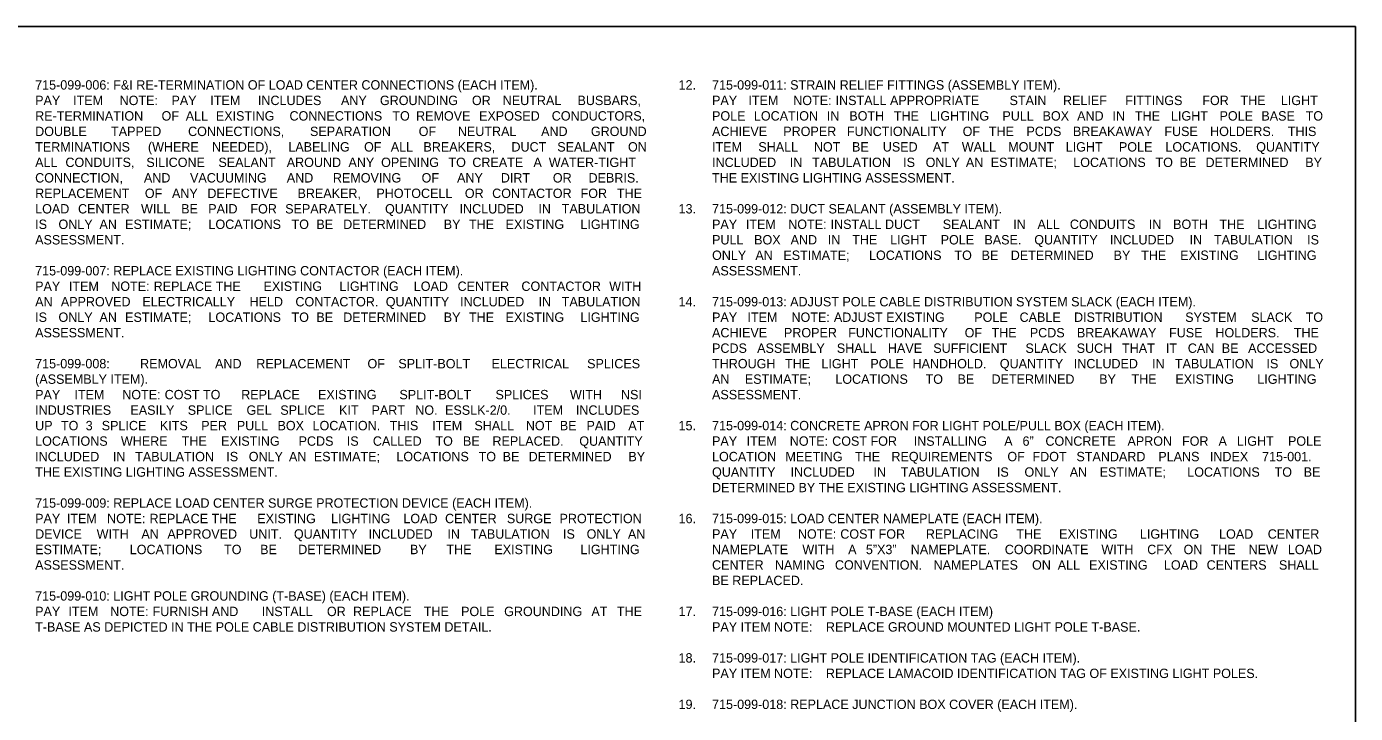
# Model space of a CAD drawing. Extents: x -55 to 2471539, y -90 to 3608906.
# Drawn here: x 549 to 1540, y 448 to 960 of the extents above; entities that cross this region are included whole.
import ezdxf

# ---------------------------------------------------------------- set-up
doc = ezdxf.new("R2010")
doc.units = 0
doc.layers.add('NonPlottingEle_dp', color=7, linetype='Continuous')
doc.layers.add('TextNotes', color=7, linetype='Continuous')

msp = doc.modelspace()

# ---------------------------------------------------------------- linework, layer by layer
at = {"layer": 'NonPlottingEle_dp'}
msp.add_lwpolyline([(0, 0), (0, 960), (1540, 960), (1540, 0)], dxfattribs=at)

# ---------------------------------------------------------------- texts
at = {"layer": 'TextNotes'}
for s, p in [('715-099-006: F&I RE-TERMINATION OF LOAD CENTER CONNECTIONS (EACH ITEM).', (555, 913)), ('12.', (1035.02, 913)), ('715-099-011: STRAIN RELIEF FITTINGS (ASSEMBLY ITEM).', (1060, 913)), ('PAY ', (555, 901.45)), ('ITEM ', (583.33, 901.45)), ('NOTE: ', (618.03, 901.45)), ('PAY ', (656.71, 901.45)), ('ITEM ', (685.68, 901.45)), ('INCLUDES ', (721.21, 901.45)), ('ANY ', (783.17, 901.45)), ('GROUNDING ', (812.22, 901.45)), ('OR ', (880.85, 901.45)), ('NEUTRAL ', (903.86, 901.45)), ('BUSBARS, ', (959.62, 901.45)), ('PAY ', (1060, 901.45)), ('ITEM ', (1087.09, 901.45)), ('NOTE:', (1120.56, 901.45)), (' INSTALL APPROPRIATE ', (1149.59, 901.45)), ('STAIN ', (1281.96, 901.45)), ('RELIEF ', (1321.82, 901.45)), ('FITTINGS ', (1368.29, 901.45)), ('FOR ', (1425.77, 901.45)), ('THE ', (1454.27, 901.45)), ('LIGHT ', (1484.37, 901.45)), ('RE-TERMINATION ', (555, 889.9)), ('OF ', (649.32, 889.9)), ('ALL ', (667.35, 889.9)), ('EXISTING ', (689.8, 889.9)), ('CONNECTIONS ', (744.75, 889.9)), ('TO ', (821.49, 889.9)), ('REMOVE ', (839.17, 889.9)), ('EXPOSED ', (886.18, 889.9)), ('CONDUCTORS, ', (940.41, 889.9)), ('POLE ', (1060, 889.9)), ('LOCATION ', (1091.23, 889.9)), ('IN ', (1145.64, 889.9)), ('BOTH ', (1162.41, 889.9)), ('THE ', (1195.61, 889.9)), ('LIGHTING ', (1222.5, 889.9)), ('PULL ', (1276.62, 889.9)), ('BOX ', (1306.59, 889.9)), ('AND ', (1332.37, 889.9)), ('IN ', (1358.72, 889.9)), ('THE ', (1375.49, 889.9)), ('LIGHT ', (1402.38, 889.9)), ('POLE ', (1438.62, 889.9)), ('BASE ', (1469.84, 889.9)), ('TO ', (1502.86, 889.9)), ('DOUBLE ', (555, 878.35)), ('TAPPED ', (611.64, 878.35)), ('CONNECTIONS, ', (669.09, 878.35)), ('SEPARATION ', (760.05, 878.35)), ('OF ', (841.16, 878.35)), ('NEUTRAL ', (870.36, 878.35)), ('AND ', (932.47, 878.35)), ('GROUND ', (969.61, 878.35)), ('ACHIEVE ', (1060, 878.35)), ('PROPER ', (1113.14, 878.35)), ('FUNCTIONALITY ', (1160.59, 878.35)), ('OF ', (1246.99, 878.35)), ('THE ', (1266.54, 878.35)), ('PCDS ', (1294.58, 878.35)), ('BREAKAWAY ', (1329.23, 878.35)), ('FUSE ', (1397.46, 878.35)), ('HOLDERS. ', (1431.57, 878.35)), ('THIS ', (1489.55, 878.35)), ('TERMINATIONS ', (555, 866.8)), ('(WHERE ', (639.14, 866.8)), ('NEEDED), ', (686.93, 866.8)), ('LABELING ', (743.91, 866.8)), ('OF ', (800.37, 866.8)), ('ALL ', (820.32, 866.8)), ('BREAKERS, ', (844.69, 866.8)), ('DUCT ', (910.35, 866.8)), ('SEALANT ', (944.54, 866.8)), ('ON ', (997.3, 866.8)), ('ITEM ', (1060, 866.8)), ('SHALL ', (1094.54, 866.8)), ('NOT ', (1135.96, 866.8)), ('BE ', (1164.42, 866.8)), ('USED ', (1187.4, 866.8)), ('AT ', (1224.78, 866.8)), ('WALL ', (1246.34, 866.8)), ('MOUNT ', (1280.97, 866.8)), ('LIGHT ', (1323.86, 866.8)), ('POLE ', (1363.56, 866.8)), ('LOCATIONS. ', (1398.25, 866.8)), ('QUANTITY ', (1465.96, 866.8)), ('ALL ', (555, 855.25)), ('CONDUITS, ', (577.58, 855.25)), ('SILICONE ', (637.96, 855.25)), ('SEALANT ', (691.72, 855.25)), ('AROUND ', (742.69, 855.25)), ('ANY ', (788.75, 855.25)), ('OPENING ', (813.1, 855.25)), ('TO ', (863.36, 855.25)), ('CREATE ', (881.17, 855.25)), ('A ', (926.74, 855.25)), ('WATER-TIGHT ', (938.22, 855.25)), ('INCLUDED ', (1060, 855.25)), ('IN ', (1117.98, 855.25)), ('TABULATION ', (1134.64, 855.25)), ('IS ', (1202.58, 855.25)), ('ONLY ', (1219.37, 855.25)), ('AN ', (1249.35, 855.25)), ('ESTIMATE; ', (1267.89, 855.25)), ('LOCATIONS ', (1329.47, 855.25)), ('TO ', (1390.85, 855.25)), ('BE ', (1408.78, 855.25)), ('DETERMINED ', (1428.18, 855.25)), ('BY ', (1502.59, 855.25)), ('CONNECTION, ', (555, 843.7)), ('AND ', (636.14, 843.7)), ('VACUUMING ', (670.54, 843.7)), ('AND ', (742.73, 843.7)), ('REMOVING ', (777.13, 843.7)), ('OF ', (843.31, 843.7)), ('ANY ', (869.77, 843.7)), ('DIRT ', (902.41, 843.7)), ('OR ', (941.24, 843.7)), ('DEBRIS. ', (967.85, 843.7)), ('THE EXISTING LIGHTING ASSESSMENT.', (1060, 843.7)), ('REPLACEMENT ', (555, 832.15)), ('OF ', (636.84, 832.15)), ('ANY ', (657.07, 832.15)), ('DEFECTIVE ', (683.49, 832.15)), ('BREAKER, ', (750.73, 832.15)), ('PHOTOCELL ', (809.59, 832.15)), ('OR ', (875.57, 832.15)), ('CONTACTOR ', (895.95, 832.15)), ('FOR ', (961.93, 832.15)), ('THE ', (989.03, 832.15)), ('LOAD ', (555, 820.6)), ('CENTER ', (586.99, 820.6)), ('WILL ', (633.99, 820.6)), ('BE ', (663.94, 820.6)), ('PAID ', (684.13, 820.6)), ('FOR ', (715.59, 820.6)), ('SEPARATELY. ', (741.53, 820.6)), ('QUANTITY ', (816.04, 820.6)), ('INCLUDED ', (871.65, 820.6)), ('IN ', (930.41, 820.6)), ('TABULATION ', (947.86, 820.6)), ('13.', (1035.02, 820.6)), ('715-099-012: DUCT SEALANT (ASSEMBLY ITEM).', (1060, 820.6)), ('IS ', (555, 809.05)), ('ONLY ', (572.4, 809.05)), ('AN ', (602.97, 809.05)), ('ESTIMATE; ', (622.11, 809.05)), ('LOCATIONS ', (684.3, 809.05)), ('TO ', (746.27, 809.05)), ('BE ', (764.81, 809.05)), ('DETERMINED ', (784.81, 809.05)), ('BY ', (859.82, 809.05)), ('THE ', (878.62, 809.05)), ('EXISTING ', (905.99, 809.05)), ('LIGHTING ', (961.79, 809.05)), ('PAY ', (1060, 809.05)), ('ITEM ', (1085.22, 809.05)), ('NOTE:', (1116.82, 809.05)), (' INSTALL DUCT ', (1145.86, 809.05)), ('SEALANT ', (1232.1, 809.05)), ('IN ', (1284.66, 809.05)), ('ALL ', (1302.79, 809.05)), ('CONDUITS ', (1326.96, 809.05)), ('IN ', (1385.87, 809.05)), ('BOTH ', (1404, 809.05)), ('THE ', (1438.55, 809.05)), ('LIGHTING ', (1466.79, 809.05)), ('ASSESSMENT.', (555, 797.5)), ('PULL ', (1060, 797.5)), ('BOX ', (1091.4, 797.5)), ('AND ', (1118.61, 797.5)), ('IN ', (1146.38, 797.5)), ('THE ', (1164.58, 797.5)), ('LIGHT ', (1192.89, 797.5)), ('POLE ', (1230.56, 797.5)), ('BASE. ', (1263.21, 797.5)), ('QUANTITY ', (1300.41, 797.5)), ('INCLUDED ', (1356.78, 797.5)), ('IN ', (1416.31, 797.5)), ('TABULATION ', (1434.51, 797.5)), ('IS ', (1503.99, 797.5)), ('ONLY ', (1060, 785.95)), ('AN ', (1092.31, 785.95)), ('ESTIMATE; ', (1113.2, 785.95)), ('LOCATIONS ', (1177.12, 785.95)), ('TO ', (1240.84, 785.95)), ('BE ', (1261.11, 785.95)), ('DETERMINED ', (1282.85, 785.95)), ('BY ', (1359.6, 785.95)), ('THE ', (1380.14, 785.95)), ('EXISTING ', (1409.25, 785.95)), ('LIGHTING ', (1466.79, 785.95)), ('715-099-007: REPLACE EXISTING LIGHTING CONTACTOR (EACH ITEM).', (555, 774.4)), ('ASSESSMENT.', (1060, 774.4)), ('PAY ', (555, 762.85)), ('ITEM ', (580.2, 762.85)), ('NOTE:', (611.78, 762.85)), (' REPLACE THE ', (640.81, 762.85)), ('EXISTING ', (725.38, 762.85)), ('LIGHTING ', (782.03, 762.85)), ('LOAD ', (837.48, 762.85)), ('CENTER ', (870.14, 762.85)), ('CONTACTOR ', (917.79, 762.85)), ('WITH ', (983.27, 762.85)), ('AN ', (555, 751.3)), ('APPROVED ', (574.15, 751.3)), ('ELECTRICALLY ', (634.99, 751.3)), ('HELD ', (714.94, 751.3)), ('CONTACTOR. ', (749.18, 751.3)), ('QUANTITY ', (816.57, 751.3)), ('INCLUDED ', (872.01, 751.3)), ('IN ', (930.59, 751.3)), ('TABULATION ', (947.86, 751.3)), ('14.', (1035.02, 751.3)), ('715-099-013: ADJUST POLE CABLE DISTRIBUTION SYSTEM SLACK (EACH ITEM).', (1060, 751.3)), ('IS ', (555, 739.75)), ('ONLY ', (572.4, 739.75)), ('AN ', (602.97, 739.75)), ('ESTIMATE; ', (622.11, 739.75)), ('LOCATIONS ', (684.3, 739.75)), ('TO ', (746.27, 739.75)), ('BE ', (764.81, 739.75)), ('DETERMINED ', (784.81, 739.75)), ('BY ', (859.82, 739.75)), ('THE ', (878.62, 739.75)), ('EXISTING ', (905.99, 739.75)), ('LIGHTING ', (961.79, 739.75)), ('PAY ', (1060, 739.75)), ('ITEM ', (1086.44, 739.75)), ('NOTE:', (1119.27, 739.75)), (' ADJUST EXISTING ', (1148.3, 739.75)), ('POLE ', (1255.64, 739.75)), ('CABLE ', (1289.44, 739.75)), ('DISTRIBUTION ', (1330.06, 739.75)), ('SYSTEM ', (1413.01, 739.75)), ('SLACK ', (1462.22, 739.75)), ('TO ', (1502.86, 739.75)), ('ASSESSMENT.', (555, 728.2)), ('ACHIEVE ', (1060, 728.2)), ('PROPER ', (1113.64, 728.2)), ('FUNCTIONALITY ', (1161.58, 728.2)), ('OF ', (1248.48, 728.2)), ('THE ', (1268.53, 728.2)), ('PCDS ', (1297.07, 728.2)), ('BREAKAWAY ', (1332.22, 728.2)), ('FUSE ', (1400.95, 728.2)), ('HOLDERS. ', (1435.55, 728.2)), ('THE ', (1494.03, 728.2)), ('PCDS ', (1060, 716.65)), ('ASSEMBLY ', (1093.64, 716.65)), ('SHALL ', (1153.08, 716.65)), ('SUFFICIENT ', (1225.08, 716.65)), ('SLACK ', (1293.82, 716.65)), ('SUCH ', (1332.03, 716.65)), ('CAN ', (1414.93, 716.65)), ('ACCESSED ', (1459.95, 716.65)), ('HAVE ', (1191.19, 716.65)), ('THAT ', (1365.89, 716.65)), ('IT ', (1398.57, 716.65)), ('BE ', (1440.29, 716.65)), ('715-099-008: ', (555, 705.1)), ('REMOVAL ', (633.3, 705.1)), ('AND ', (689.22, 705.1)), ('REPLACEMENT ', (719.97, 705.1)), ('OF ', (802.94, 705.1)), ('SPLIT-BOLT ', (825.96, 705.1)), ('ELECTRICAL ', (895.53, 705.1)), ('SPLICES ', (966.8, 705.1)), ('THROUGH ', (1060, 705.1)), ('THE ', (1114.45, 705.1)), ('LIGHT ', (1141.6, 705.1)), ('POLE ', (1178.1, 705.1)), ('HANDHOLD. ', (1209.59, 705.1)), ('QUANTITY ', (1274.7, 705.1)), ('INCLUDED ', (1329.91, 705.1)), ('IN ', (1388.27, 705.1)), ('TABULATION ', (1405.31, 705.1)), ('IS ', (1473.64, 705.1)), ('ONLY ', (1490.82, 705.1)), ('(ASSEMBLY ITEM).', (555, 693.55)), ('AN ', (1060, 693.55)), ('ESTIMATE; ', (1084.47, 693.55)), ('LOCATIONS ', (1151.99, 693.55)), ('TO ', (1219.29, 693.55)), ('BE ', (1243.16, 693.55)), ('DETERMINED ', (1268.49, 693.55)), ('BY ', (1348.83, 693.55)), ('THE ', (1372.96, 693.55)), ('EXISTING ', (1405.66, 693.55)), ('LIGHTING ', (1466.79, 693.55)), ('PAY ', (555, 682)), ('ITEM ', (584.31, 682)), ('NOTE:', (619.99, 682)), (' COST TO ', (649.03, 682)), ('REPLACE ', (708.72, 682)), ('EXISTING ', (766, 682)), ('SPLIT-BOLT ', (826.76, 682)), ('SPLICES ', (898.44, 682)), ('WITH ', (953.99, 682)), ('NSI ', (992.06, 682)), ('ASSESSMENT.', (1060, 682)), ('INDUSTRIES ', (555, 670.45)), ('EASILY ', (626.07, 670.45)), ('SPLICE ', (668.84, 670.45)), ('GEL ', (712.69, 670.45)), ('SPLICE ', (737.91, 670.45)), ('KIT ', (781.76, 670.45)), ('PART ', (805.95, 670.45)), ('NO. ', (838.61, 670.45)), ('ESSLK-2/0. ', (860.81, 670.45)), ('ITEM ', (926.52, 670.45)), ('INCLUDES ', (958.42, 670.45)), ('UP ', (555, 658.9)), ('TO ', (574.26, 658.9)), ('3 ', (592.69, 658.9)), ('SPLICE ', (604.66, 658.9)), ('KITS ', (648.07, 658.9)), ('PER ', (678.89, 658.9)), ('PULL ', (705.45, 658.9)), ('BOX ', (735.81, 658.9)), ('LOCATION. ', (761.97, 658.9)), ('THIS ', (819.52, 658.9)), ('ITEM ', (851.26, 658.9)), ('SHALL ', (882.71, 658.9)), ('NOT ', (921.06, 658.9)), ('BE ', (946.43, 658.9)), ('PAID ', (966.33, 658.9)), ('AT ', (997.51, 658.9)), ('15.', (1035.02, 658.9)), ('715-099-014: CONCRETE APRON FOR LIGHT POLE/PULL BOX (EACH ITEM).', (1060, 658.9)), ('LOCATIONS ', (555, 647.35)), ('WHERE ', (618.98, 647.35)), ('THE ', (664.35, 647.35)), ('EXISTING ', (693.73, 647.35)), ('PCDS ', (751.54, 647.35)), ('IS ', (787.53, 647.35)), ('CALLED ', (806.94, 647.35)), ('TO ', (853.63, 647.35)), ('BE ', (874.17, 647.35)), ('REPLACED. ', (896.18, 647.35)), ('QUANTITY ', (960.96, 647.35)), ('PAY ', (1060, 647.35)), ('ITEM ', (1085.81, 647.35)), ('NOTE:', (1118, 647.35)), (' COST FOR ', (1147.03, 647.35)), ('INSTALLING ', (1210.44, 647.35)), ('A ', (1278, 647.35)), ('6” ', (1291.66, 647.35)), ('CONCRETE ', (1308.73, 647.35)), ('APRON ', (1369.93, 647.35)), ('FOR ', (1410.64, 647.35)), ('A ', (1437.85, 647.35)), ('LIGHT ', (1451.51, 647.35)), ('POLE ', (1489.69, 647.35)), ('INCLUDED ', (555, 635.8)), ('IN ', (612.98, 635.8)), ('TABULATION ', (629.64, 635.8)), ('IS ', (697.58, 635.8)), ('ONLY ', (714.37, 635.8)), ('AN ', (744.35, 635.8)), ('ESTIMATE; ', (762.89, 635.8)), ('LOCATIONS ', (824.47, 635.8)), ('TO ', (885.85, 635.8)), ('BE ', (903.78, 635.8)), ('DETERMINED ', (923.18, 635.8)), ('BY ', (997.59, 635.8)), ('LOCATION ', (1060, 635.8)), ('MEETING ', (1114.74, 635.8)), ('THE ', (1166.62, 635.8)), ('REQUIREMENTS ', (1193.83, 635.8)), ('OF ', (1280.34, 635.8)), ('FDOT ', (1299.06, 635.8)), ('STANDARD ', (1331.84, 635.8)), ('PLANS ', (1392.94, 635.8)), ('INDEX ', (1431.42, 635.8)), ('715-001. ', (1470.36, 635.8)), ('THE EXISTING LIGHTING ASSESSMENT.', (555, 624.25)), ('QUANTITY ', (1060, 624.25)), ('INCLUDED ', (1118.61, 624.25)), ('IN ', (1180.37, 624.25)), ('TABULATION ', (1200.8, 624.25)), ('IS ', (1272.52, 624.25)), ('ONLY ', (1293.09, 624.25)), ('AN ', (1326.85, 624.25)), ('ESTIMATE; ', (1349.17, 624.25)), ('LOCATIONS ', (1414.53, 624.25)), ('TO ', (1479.68, 624.25)), ('BE ', (1501.39, 624.25)), ('DETERMINED BY THE EXISTING LIGHTING ASSESSMENT.', (1060, 612.7)), ('715-099-009: REPLACE LOAD CENTER SURGE PROTECTION DEVICE (EACH ITEM).', (555, 601.15)), ('PAY ', (555, 589.6)), ('ITEM ', (578.64, 589.6)), ('NOTE:', (608.67, 589.6)), (' REPLACE THE ', (637.71, 589.6)), ('EXISTING ', (720.72, 589.6)), ('LIGHTING ', (775.82, 589.6)), ('LOAD ', (829.71, 589.6)), ('CENTER ', (860.82, 589.6)), ('SURGE ', (906.92, 589.6)), ('PROTECTION ', (946.21, 589.6)), ('16.', (1035.02, 589.6)), ('715-099-015: LOAD CENTER NAMEPLATE (EACH ITEM).', (1060, 589.6)), ('DEVICE ', (555, 578.05)), ('WITH ', (600.91, 578.05)), ('AN ', (634.26, 578.05)), ('APPROVED ', (653.64, 578.05)), ('UNIT. ', (714.71, 578.05)), ('QUANTITY ', (748.05, 578.05)), ('INCLUDED ', (803.71, 578.05)), ('IN ', (862.53, 578.05)), ('TABULATION ', (880.03, 578.05)), ('IS ', (948.81, 578.05)), ('ONLY ', (966.44, 578.05)), ('AN ', (997.25, 578.05)), ('PAY ', (1060, 578.05)), ('ITEM ', (1088.83, 578.05)), ('NOTE:', (1124.05, 578.05)), (' COST FOR ', (1153.08, 578.05)), ('REPLACING ', (1219.52, 578.05)), ('THE ', (1287.07, 578.05)), ('EXISTING ', (1318.92, 578.05)), ('LIGHTING ', (1379.21, 578.05)), ('LOAD ', (1438.29, 578.05)), ('CENTER ', (1474.58, 578.05)), ('ESTIMATE; ', (555, 566.5)), ('LOCATIONS ', (625.58, 566.5)), ('TO ', (695.94, 566.5)), ('BE ', (722.86, 566.5)), ('DETERMINED ', (751.25, 566.5)), ('BY ', (834.65, 566.5)), ('THE ', (861.84, 566.5)), ('EXISTING ', (897.6, 566.5)), ('LIGHTING ', (961.79, 566.5)), ('NAMEPLATE ', (1060, 566.5)), ('WITH ', (1127.38, 566.5)), ('A ', (1161.54, 566.5)), ('5”X3” ', (1174.78, 566.5)), ('NAMEPLATE. ', (1208.27, 566.5)), ('COORDINATE ', (1278.41, 566.5)), ('WITH ', (1350.49, 566.5)), ('CFX ', (1384.65, 566.5)), ('ON ', (1411.78, 566.5)), ('THE ', (1431.92, 566.5)), ('NEW ', (1460.33, 566.5)), ('LOAD ', (1489.58, 566.5)), ('ASSESSMENT.', (555, 554.95)), ('CENTER ', (1060, 554.95)), ('NAMING ', (1106.87, 554.95)), ('CONVENTION. ', (1151.67, 554.95)), ('NAMEPLATES ', (1225.27, 554.95)), ('ON ', (1298.74, 554.95)), ('ALL ', (1317.9, 554.95)), ('EXISTING ', (1341.26, 554.95)), ('LOAD ', (1397.13, 554.95)), ('CENTERS ', (1428.99, 554.95)), ('SHALL ', (1482.94, 554.95)), ('BE REPLACED.', (1060, 543.4)), ('715-099-010: LIGHT POLE GROUNDING (T-BASE) (EACH ITEM).', (555, 531.85)), ('PAY ', (555, 520.3)), ('ITEM ', (579.8, 520.3)), ('NOTE:', (610.97, 520.3)), (' FURNISH AND ', (640.01, 520.3)), ('INSTALL ', (724.02, 520.3)), ('OR ', (772.68, 520.3)), ('REPLACE ', (792.17, 520.3)), ('THE ', (844.94, 520.3)), ('POLE ', (872.75, 520.3)), ('GROUNDING ', (904.9, 520.3)), ('AT ', (970, 520.3)), ('THE ', (989.03, 520.3)), ('17.', (1035.02, 520.3)), ('715-099-016: LIGHT POLE T-BASE (EACH ITEM)', (1060, 520.3)), ('T-BASE AS DEPICTED IN THE POLE CABLE DISTRIBUTION SYSTEM DETAIL.', (555, 508.75)), ('PAY ITEM NOTE:', (1060, 508.75)), (' REPLACE GROUND MOUNTED LIGHT POLE T-BASE.', (1142.35, 508.75)), ('18.', (1035.02, 485.65)), ('715-099-017: LIGHT POLE IDENTIFICATION TAG (EACH ITEM).', (1060, 485.65)), ('PAY ITEM NOTE:', (1060, 474.1)), (' REPLACE LAMACOID IDENTIFICATION TAG OF EXISTING LIGHT POLES.', (1142.35, 474.1)), ('19.', (1035.02, 451)), ('715-099-018: REPLACE JUNCTION BOX COVER (EACH ITEM).', (1060, 451))]:
    msp.add_text(s, height=7, dxfattribs=at).set_placement(p)

doc.saveas('drawing.dxf')
